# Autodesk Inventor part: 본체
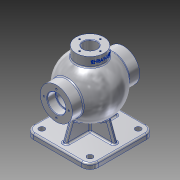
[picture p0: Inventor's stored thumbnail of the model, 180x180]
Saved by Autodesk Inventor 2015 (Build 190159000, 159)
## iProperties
Created: 2025-08
Part Number: 본체
Material: 알루미늄 6061
Document SubType Name: Modeling
Designer: user
Density: 2.7 g/cm^3
Appearance: 알루미늄 - 평지
Author: user
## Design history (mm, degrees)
sketch "스케치1"
  geometry: L1 (-62.5, 62.5)-(62.5, 62.5); L2 (62.5, 62.5)-(62.5, -62.5); L3 (62.5, -62.5)-(-62.5, -62.5); L4 (-62.5, -62.5)-(-62.5, 62.5); 3 further points
  constraints: 8 end point, 2 midpoint, 2 parallel, 1 horizontal, 1 horizontal alignment, 1 perpendicular, 1 vertical alignment
  dimensions: "d0" = 125 distance of L2.end L3.end; "d1" = 125 distance of L1.end L2.end
extrude "돌출1" new body sketch "스케치1" distance "d2" = 10; taper "d3" = 0 deg
node "작업 평면1"
sketch "스케치3"
  geometry: L1 (54, 0)-(44, 0); L2 (-44, 0)-(-54, 0); A1 r 54 centre (0, 0) between (-54, 0) and (54, 0); A2 r 44 centre (0, 0) between (-44, 0) and (44, 0); 1 further point
  constraints: 4 end point, 4 point on circle, 2 centre point, 2 coincident, 2 horizontal
  dimensions: "d9" = 108 diameter of A1; "d10" = 88 diameter of A2; "d11" = 108 distance of L1.start L2.end; "d12" = 10 distance of L2.start L2.end
revolve "회전2" sketch "스케치3" stored, may be unused: angle "d13" = 90 deg
sketch "스케치4"
  geometry: L1 (4, -50.5)-(-4, -50.5); L2 (-4, -50.5)-(-4, 50.5); L3 (-4, 50.5)-(4, 50.5); L4 (4, 50.5)-(4, -50.5); L5 (50.5, -4)-(-50.5, -4); L6 (-50.5, -4)-(-50.5, 4); L7 (-50.5, 4)-(50.5, 4); L8 (50.5, 4)-(50.5, -4); L9 (62.5, 62.5)-(62.5, -62.5) reference; L10 (-62.5, -62.5)-(-62.5, 62.5) reference; L11 (62.5, -62.5)-(-62.5, -62.5) reference; L12 (-62.5, 62.5)-(62.5, 62.5) reference; 3 further points
  constraints: 16 end point, 4 parallel, 2 horizontal, 2 midpoint, 2 perpendicular, 1 horizontal alignment, 1 vertical alignment
  dimensions: "d14" = 8 distance of L1.start L1.end; "d15" = 8 distance of L5.end L6.end; "d16" = 12 distance between parallel lines of L9 L8; "d17" = 12 distance between parallel lines of L10 L6; "d18" = 12 distance between parallel lines of L11 L1; "d19" = 12 distance between parallel lines of L12 L3
extrude "돌출2" join sketch "스케치4" stored distance "d20" = 10; taper "d21" = 0 deg
feature "면 기울기1" dims angle "d22" = 20 deg
feature "면 기울기2" dims angle "d23" = 20 deg
feature "면 기울기3" dims angle "d24" = 20 deg
feature "면 기울기4" dims angle "d25" = 20 deg
node "작업 평면3"
sketch "스케치5"
  geometry: L1 (37.329, 46.186)-(37.329, 46.186) reference; L2 (4, 31.297)-(4, 46.186) reference; L3 (-4, 46.186)-(-4, 31.297) reference; L4 (-37.329, 46.186)-(-37.329, 46.186) reference; L5 (-4, 31.297)-(-4, 46.186) reference; L6 (4, 46.186)-(4, 31.297) reference; C1 r 31 at (0, 85); A1 r 53.852 centre (0, 85) between (4, 31.297) and (37.329, 46.186) reference; A2 r 53.852 centre (0, 85) between (-37.329, 46.186) and (-4, 31.297) reference; A3 r 53.852 centre (0, 85) between (-37.329, 46.186) and (-4, 31.297) reference; A4 r 53.852 centre (0, 85) between (4, 31.297) and (37.329, 46.186) reference; 3 further points; 2 other entities
  constraints: 1 centre point, 1 coincident, 2 other
  dimensions: "d28" = 62 diameter of C1
extrude "돌출3" join sketch "스케치5" stored distance "d29" = 10; taper "d30" = 0 deg
hole "구멍1" diameter "d33" = 30; stored, may be unused: countersink angle "d37" = 90 deg, drill point angle "d39" = 0 deg; dims "d34" = 6, "d35" = 35, "d36" = 16, "d38" = 65, "d40" = 10, "d41" = 10
node "작업 평면4"
sketch "스케치6"
  geometry: C1 r 27 at (0, 0); 1 further point
  constraints: 1 centre point, 1 coincident
  dimensions: "d43" = 54 diameter of C1
extrude "돌출4" join sketch "스케치6" stored distance "d44" = 10; taper "d45" = 0 deg
hole "구멍2" diameter "d48" = 26; stored, may be unused: countersink angle "d52" = 90 deg, drill point angle "d54" = 0 deg; dims "d46" = 10, "d47" = 10, "d49" = 6, "d50" = 35, "d51" = 16, "d53" = 8
fillet "모깎기1" dims "d55" = 16
hole "구멍3" diameter "d58" = 11; stored, may be unused: countersink angle "d62" = 90 deg, drill point angle "d64" = 0 deg; dims "d56" = 10, "d57" = 10, "d59" = 6, "d60" = 35, "d61" = 16, "d63" = 8
node "작업 평면5"
sketch "스케치7"
  geometry: L1 (-27, 131.765)-(27, 131.765) reference; L2 (-27, 150)-(27, 150) reference; L3 (-27, 150)-(-27, 131.765) reference; L4 (13, 127.036)-(-13, 127.036) reference; L5 (41.364, 70)-(41.364, 100) reference; L6 (-41.364, 100)-(-41.364, 70) reference; A1 r 54 centre (0, 85) between (37.385, 46.034) and (-37.385, 46.034) reference; 2 further points
  constraints: 1 vertical alignment, 1 other
  dimensions: "d73" = 9 distance from line of L2 point (0, 141)
feature "엠보싱1" sketch "스케치7" dims "d14" = 8, "d18" = 12, "d19" = 12, "d74" = 1, "d75" = 0
sketch "스케치8"
  geometry: L1 (0, 0)-(0, 24); A1 r 54 centre (0, 0) between (37.385, -38.966) and (-37.385, -38.966) reference; 1 further point
  constraints: 2 end point, 1 vertical
  dimensions: "d76" = 24 distance of L1.start L1.end
hole "구멍4" sketch "스케치8" at (0, 24) diameter "d77" = 3.242; stored, may be unused: countersink angle "d81" = 90 deg, drill point angle "d83" = 118 deg; dims "d78" = 12, "d79" = 35, "d80" = 16, "d82" = 15
sketch "스케치9"
  geometry: L1 (0, 0)-(0, 20); C1 r 27 at (0, 0) reference; 1 further point
  constraints: 2 end point, 1 vertical
  dimensions: "d87" = 20 distance of L1.start L1.end
hole "구멍5" sketch "스케치9" at (0, 20) diameter "d88" = 3.242; stored, may be unused: countersink angle "d92" = 90 deg, drill point angle "d94" = 118 deg; dims "d89" = 9, "d90" = 35, "d91" = 16, "d93" = 11
fillet "모깎기2" dims "d98" = 0.6
chamfer "모따기1" distance "d99" = 1; stored, may be unused: second distance "d100" = 2, angle "d101" = 45 deg
fillet "모깎기3" dims "d102" = 3
fillet "모깎기4" dims "d103" = 3
fillet "모깎기5" dims "d104" = 3
node "솔리드1"
mirror "대칭1"
pattern_linear "직사각형 패턴1" dims "d67" = 93, "d70" = 93
pattern_circular "원형 패턴1" dims angle "d85" = 360 deg
mirror "대칭2"
pattern_circular "원형 패턴2" dims angle "d96" = 360 deg
node "투영된 루프1"
node "투영된 루프2"
node "투영된 루프3"
other parameters: "d4" = 85, "d27" = -65, "d71" = 13
